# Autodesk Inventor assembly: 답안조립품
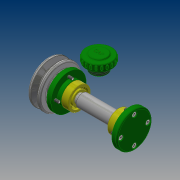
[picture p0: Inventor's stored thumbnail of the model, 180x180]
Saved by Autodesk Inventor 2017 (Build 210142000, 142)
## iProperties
Part Number: 답안조립품
Material: 일반
Document SubType Name: Assembly
Designer: 20
Author: 20
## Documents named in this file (14)
- C:\Users\20\Desktop\470818V1004\답안조립품.iam
- C:\Users\20\Desktop\470818V1004\본체.ipt
- C:\Users\20\Desktop\470818V1004\뒤커버.ipt
- C:\Users\20\Desktop\470818V1004\앞커버.ipt
- C:\Users\20\Desktop\470818V1004\상부캡.ipt
- C:\Users\20\Desktop\470818V1004\볼트 M4 x 10.ipt
- C:\Users\20\Desktop\470818V1004\베어링 15 x 35 x 11.ipt
- C:\Users\20\Desktop\470818V1004\축.ipt
- C:\Users\20\Desktop\470818V1004\멈춤링 15 x 1.ipt
- C:\Users\20\Desktop\470818V1004\오일실 15 25 7.ipt
- C:\Users\20\Desktop\470818V1004\V-벨트풀리.ipt
- C:\Users\20\Desktop\470818V1004\키 5 x 5 x 14.ipt
- C:\Users\20\Desktop\470818V1004\와셔.ipt
- C:\Users\20\Desktop\470818V1004\볼트 M6 x 12.ipt
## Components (1 placed, 1 different names)
1. V-벨트풀리:1 — 플러쉬:1
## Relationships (1: Flush 1)
- 플러쉬:1 [Flush]: V-벨트풀리:1
